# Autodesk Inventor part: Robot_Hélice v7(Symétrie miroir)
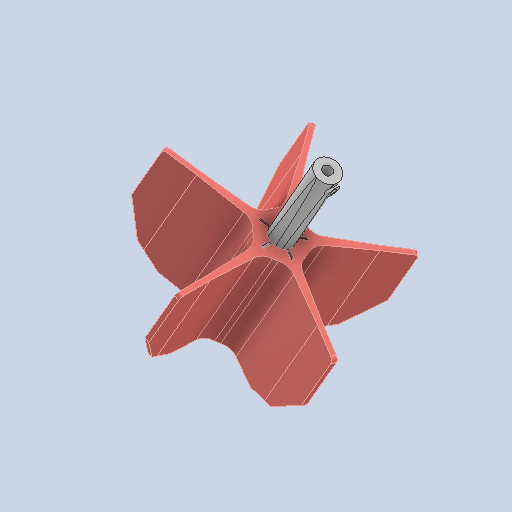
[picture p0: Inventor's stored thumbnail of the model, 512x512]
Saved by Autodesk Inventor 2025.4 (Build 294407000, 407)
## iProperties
Created: 2026-06
Part Number: Robot_Hélice v7(Symétrie miroir)
Material: Generic
Document SubType Name: Modeling
Designer: AdminForWorker
Density: 1 g/cm^3
Appearance: Default
Title: Robot_Hélice v7(Symétrie miroir)
Author: AdminForWorker
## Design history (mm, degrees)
feature "Hélice"
feature "Hélice (1)"
body "Solid1"
body "Solid2"
